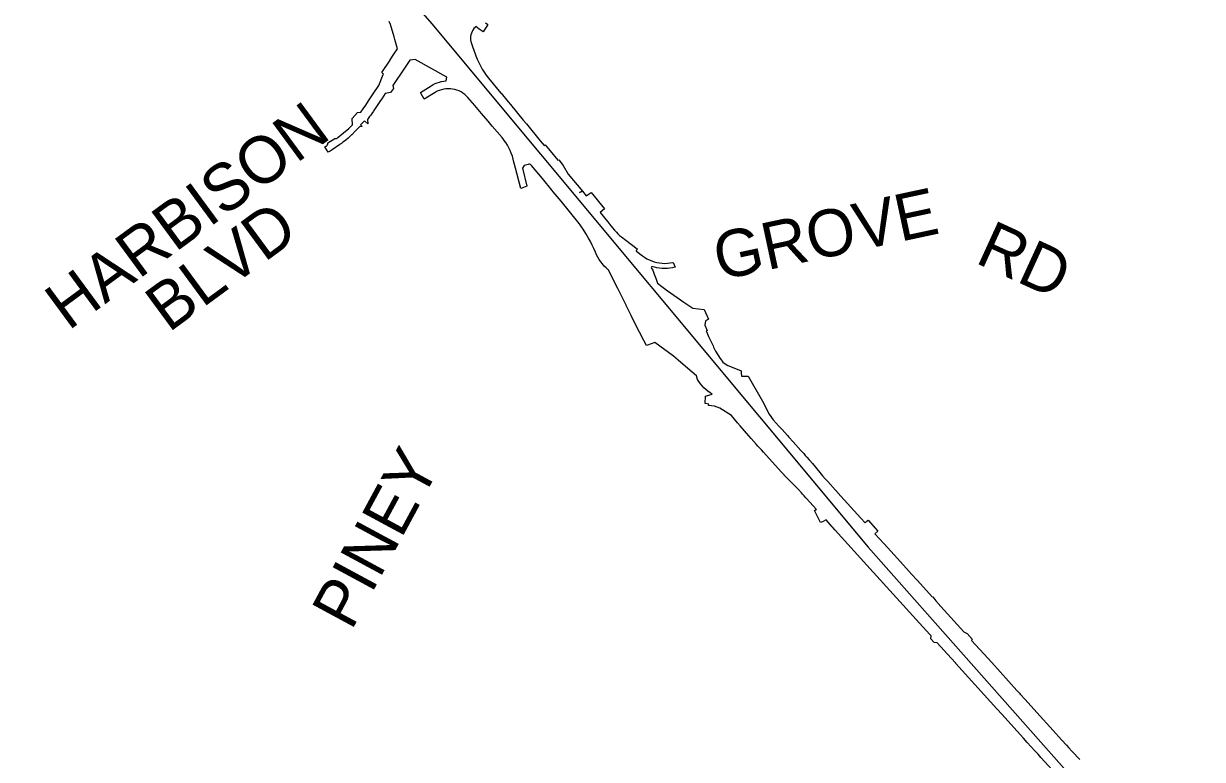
# Model space of a CAD drawing. Extents: x 1936118 to 1997618, y 780614 to 828614.
# Drawn here: x 1948606 to 1963667, y 807292 to 816697 of the extents above; entities that cross this region are included whole.
import ezdxf

# ---------------------------------------------------------------- set-up
doc = ezdxf.new("R2010")
doc.units = 0
for name, color, linetype in [('RD_EX_H2O_BlueLn', 7, 'Continuous'), ('RD_SHT_Misc3', 7, 'Continuous'), ('RD_SHT_Misc4', 7, 'Continuous')]:
    doc.layers.add(name, color=color, linetype=linetype)

msp = doc.modelspace()

# ---------------------------------------------------------------- linework, layer by layer
at = {"layer": 'RD_EX_H2O_BlueLn'}
for points in [[(1961748, 807157), (1961603, 807318), (1961567, 807358), (1961530, 807399), (1961476, 807459), (1961430, 807510), (1961380, 807565), (1961220, 807741), (1961109, 807865), (1961041, 807939), (1960517, 808519), (1960516, 808520), (1960458, 808584), (1960278, 808784), (1960242, 808786), (1960198, 808835), (1960200, 808870), (1960183, 808888), (1960011, 809078), (1960009, 809081), (1959467, 809680), (1959462, 809685), (1958977, 810222), (1958945, 810257), (1958939, 810263), (1958859, 810352), (1958812, 810329), (1958789, 810319), (1958712, 810475), (1958734, 810487), (1958736, 810488), (1958611, 810627), (1958601, 810637), (1958581, 810659), (1958560, 810682), (1958558, 810684), (1958544, 810700), (1958505, 810740), (1958365, 810883), (1958325, 810926), (1958323, 810928), (1958285, 810969), (1958060, 811217), (1958033, 811248), (1958030, 811251), (1957988, 811297), (1957967, 811320), (1957901, 811395), (1957873, 811426), (1957760, 811557), (1957728, 811594), (1957649, 811689), (1957503, 811783), (1957468, 811795), (1957433, 811805), (1957396, 811812), (1957359, 811817), (1957361, 811834), (1957338, 811837), (1957315, 811839), (1957317, 811936), (1957405, 811961), (1957377, 811979), (1957349, 811998), (1957323, 812020), (1957299, 812043), (1957275, 812067), (1957254, 812093), (1957234, 812120), (1957215, 812148), (1957202, 812195), (1957093, 812289), (1957093, 812289), (1956969, 812394), (1956908, 812446), (1956909, 812446), (1956670, 812621), (1956577, 812588), (1956564, 812584), (1956533, 812647), (1956476, 812754), (1956379, 812945), (1956369, 812966), (1956306, 813092), (1956304, 813097), (1956197, 813311), (1956123, 813460), (1956078, 813549), (1956077, 813551), (1956051, 813574), (1956026, 813598), (1956002, 813625), (1955980, 813652), (1955961, 813681), (1955943, 813712), (1955927, 813743), (1955913, 813775), (1955893, 813821), (1955872, 813866), (1955849, 813910), (1955824, 813953), (1955790, 814012), (1955755, 814069), (1955744, 814085), (1955718, 814125), (1955706, 814140), (1955473, 814428), (1955373, 814548), (1955361, 814564), (1955235, 814716), (1955096, 814884), (1955089, 814890), (1955081, 814895), (1955072, 814898), (1955063, 814899), (1955053, 814897), (1955000, 814884), (1954979, 814847), (1955037, 814617), (1954973, 814595), (1954959, 814590), (1954892, 814850), (1954867, 814943), (1954862, 814965), (1954851, 815002), (1954838, 815039), (1954823, 815075), (1954806, 815110), (1954787, 815144), (1954766, 815177), (1954744, 815208), (1954744, 815209), (1954719, 815239), (1954595, 815385), (1954540, 815450), (1954456, 815549), (1954370, 815650), (1954284, 815750), (1954264, 815771), (1954243, 815790), (1954220, 815808), (1954196, 815823), (1954170, 815836), (1954143, 815846), (1954116, 815855), (1954088, 815860), (1954059, 815864), (1954031, 815864), (1954002, 815863), (1953974, 815858), (1953946, 815852), (1953918, 815842), (1953892, 815831), (1953867, 815817), (1953726, 815731), (1953721, 815740), (1953686, 815800), (1953686, 815800), (1953676, 815817), (1953815, 815902), (1953840, 815916), (1953866, 815929), (1953892, 815939), (1953920, 815948), (1953947, 815955), (1953976, 815960), (1954004, 815963), (1954004, 815964), (1954015, 816011), (1953608, 816238), (1953541, 816230), (1953514, 816189), (1953472, 816126), (1953324, 815904), (1953331, 815868), (1953331, 815868), (1953293, 815814), (1953226, 815801), (1953182, 815735), (1953167, 815713), (1953083, 815586), (1953077, 815577), (1953056, 815547), (1953042, 815528), (1953028, 815508), (1952999, 815471), (1953003, 815417), (1952965, 815450), (1952954, 815445), (1952935, 815427), (1952909, 815403), (1952931, 815383), (1952897, 815377), (1952849, 815325), (1952799, 815275), (1952798, 815274), (1952755, 815234), (1952755, 815234), (1952725, 815207), (1952694, 815187), (1952683, 815178), (1952681, 815176), (1952672, 815169), (1952667, 815165), (1952653, 815155), (1952648, 815151), (1952549, 815083), (1952522, 815067), (1952500, 815053), (1952455, 815120), (1952472, 815130), (1952475, 815131), (1952479, 815135), (1952484, 815140), (1952487, 815145), (1952490, 815150), (1952493, 815156), (1952494, 815162), (1952495, 815168), (1952495, 815174), (1952583, 815228), (1952587, 815227), (1952592, 815227), (1952594, 815227), (1952600, 815228), (1952606, 815230), (1952612, 815232), (1952617, 815235), (1952622, 815239), (1952721, 815322), (1952721, 815322), (1952756, 815351), (1952762, 815358), (1952763, 815357), (1952792, 815384), (1952810, 815401), (1952805, 815482), (1952840, 815521), (1952874, 815562), (1952914, 815565), (1952947, 815609), (1952979, 815655), (1953014, 815708), (1953015, 815710), (1953049, 815762), (1953074, 815799), (1953145, 815905), (1953201, 816045), (1953203, 816050), (1953182, 816070), (1953289, 816231), (1953290, 816233), (1953339, 816306), (1953383, 816372), (1953349, 816494), (1953340, 816526), (1953295, 816686), (1953276, 816725)], [(1954506, 816707), (1954538, 816684), (1954526, 816665), (1954489, 816611), (1954477, 816592), (1954429, 816626), (1954407, 816642), (1954397, 816651), (1954386, 816659), (1954378, 816651), (1954375, 816648), (1954360, 816632), (1954347, 816614), (1954337, 816595), (1954328, 816574), (1954322, 816553), (1954318, 816531), (1954317, 816509), (1954318, 816487), (1954322, 816466), (1954328, 816444), (1954339, 816415), (1954386, 816284), (1954403, 816241), (1954422, 816198), (1954443, 816156), (1954466, 816116), (1954484, 816087), (1954491, 816076), (1954518, 816038), (1954547, 816001), (1954705, 815809), (1954707, 815807), (1954799, 815696), (1954827, 815662), (1954990, 815464), (1955032, 815414), (1955208, 815200), (1955258, 815140), (1955269, 815149), (1955312, 815097), (1955434, 814949), (1955443, 814957), (1955502, 814883), (1955566, 814774), (1955566, 814774), (1955747, 814554), (1955708, 814536), (1955747, 814554), (1955795, 814496), (1955857, 814539), (1956029, 814331), (1955971, 814283), (1956067, 814166), (1956072, 814161), (1956111, 814113), (1956157, 814057), (1956160, 814054), (1956180, 814032), (1956200, 814010), (1956222, 813990), (1956245, 813972), (1956301, 813928), (1956445, 813816), (1956431, 813786), (1956436, 813782), (1956441, 813785), (1956512, 813730), (1956539, 813710), (1956569, 813692), (1956599, 813676), (1956631, 813663), (1956663, 813652), (1956696, 813643), (1956730, 813637), (1956764, 813633), (1956798, 813632), (1956832, 813633), (1956866, 813637), (1956900, 813644), (1956907, 813645), (1956907, 813645), (1956931, 813583), (1956898, 813576), (1956865, 813570), (1956832, 813567), (1956799, 813566), (1956765, 813567), (1956732, 813570), (1956699, 813575), (1956667, 813582), (1956635, 813591), (1956623, 813576), (1956644, 813544), (1956663, 813495), (1956687, 813431), (1956706, 813379), (1956760, 813335), (1956811, 813297), (1956815, 813293), (1956872, 813254), (1957044, 813138), (1957159, 813060), (1957300, 813043), (1957359, 812920), (1957317, 812898), (1957311, 812842), (1957338, 812774), (1957327, 812770), (1957332, 812759), (1957358, 812698), (1957386, 812639), (1957416, 812580), (1957421, 812560), (1957448, 812511), (1957477, 812462), (1957507, 812415), (1957510, 812411), (1957539, 812368), (1957539, 812368), (1957558, 812357), (1957605, 812328), (1957616, 812321), (1957616, 812321), (1957776, 812259), (1957776, 812259), (1957776, 812259), (1957776, 812257), (1957775, 812233), (1957775, 812227), (1957777, 812191), (1957865, 812191), (1958047, 811871), (1958134, 811704), (1958185, 811631), (1958260, 811548), (1958297, 811508), (1958367, 811430), (1958383, 811411), (1958437, 811352), (1958537, 811242), (1958574, 811201), (1958594, 811178), (1958613, 811157), (1958643, 811121), (1958651, 811113), (1958685, 811072), (1958779, 810959), (1958815, 810917), (1958849, 810879), (1958853, 810875), (1958882, 810842), (1958979, 810735), (1958982, 810732), (1958983, 810731), (1959049, 810658), (1959303, 810377), (1959359, 810315), (1959359, 810315), (1959380, 810335), (1959396, 810349), (1959521, 810210), (1959484, 810177), (1959539, 810116), (1959601, 810047), (1959730, 809905), (1959887, 809731), (1959951, 809660), (1959952, 809660), (1960021, 809583), (1960219, 809364), (1960224, 809368), (1960260, 809320), (1960325, 809247), (1960620, 808921), (1960662, 808900), (1960727, 808829), (1960718, 808812), (1960924, 808585), (1960975, 808529), (1961297, 808173), (1961298, 808172), (1961330, 808137), (1961341, 808124), (1961403, 808056), (1961552, 807890), (1961760, 807660), (1961866, 807544), (1961870, 807539), (1961931, 807472), (1961960, 807440), (1961998, 807398), (1962000, 807397), (1962101, 807289)]]:
    msp.add_lwpolyline(points, dxfattribs=at)
at = {"layer": 'RD_SHT_Misc4'}
for p, q in [((1944377, 827509), (1953823, 816695)), ((1953823, 816695), (1959396, 810005)), ((1959396, 810005), (1966734, 801722))]:
    msp.add_line(p, q, dxfattribs=at)

# ---------------------------------------------------------------- texts
at = {"layer": 'RD_SHT_Misc3'}
for s, rotation, p in [('HARBISON', 36.3158, (1949179, 812764)), ('GROVE', 12.0763, (1957496, 813413)), ('BLVD', 36.3158, (1950460, 812740)), ('RD', 335.4217, (1960748, 813647)), ('PINEY', 61.6237, (1952795, 808927))]:
    msp.add_text(s, height=600, rotation=rotation, dxfattribs=at).set_placement(p)

doc.saveas('drawing.dxf')
